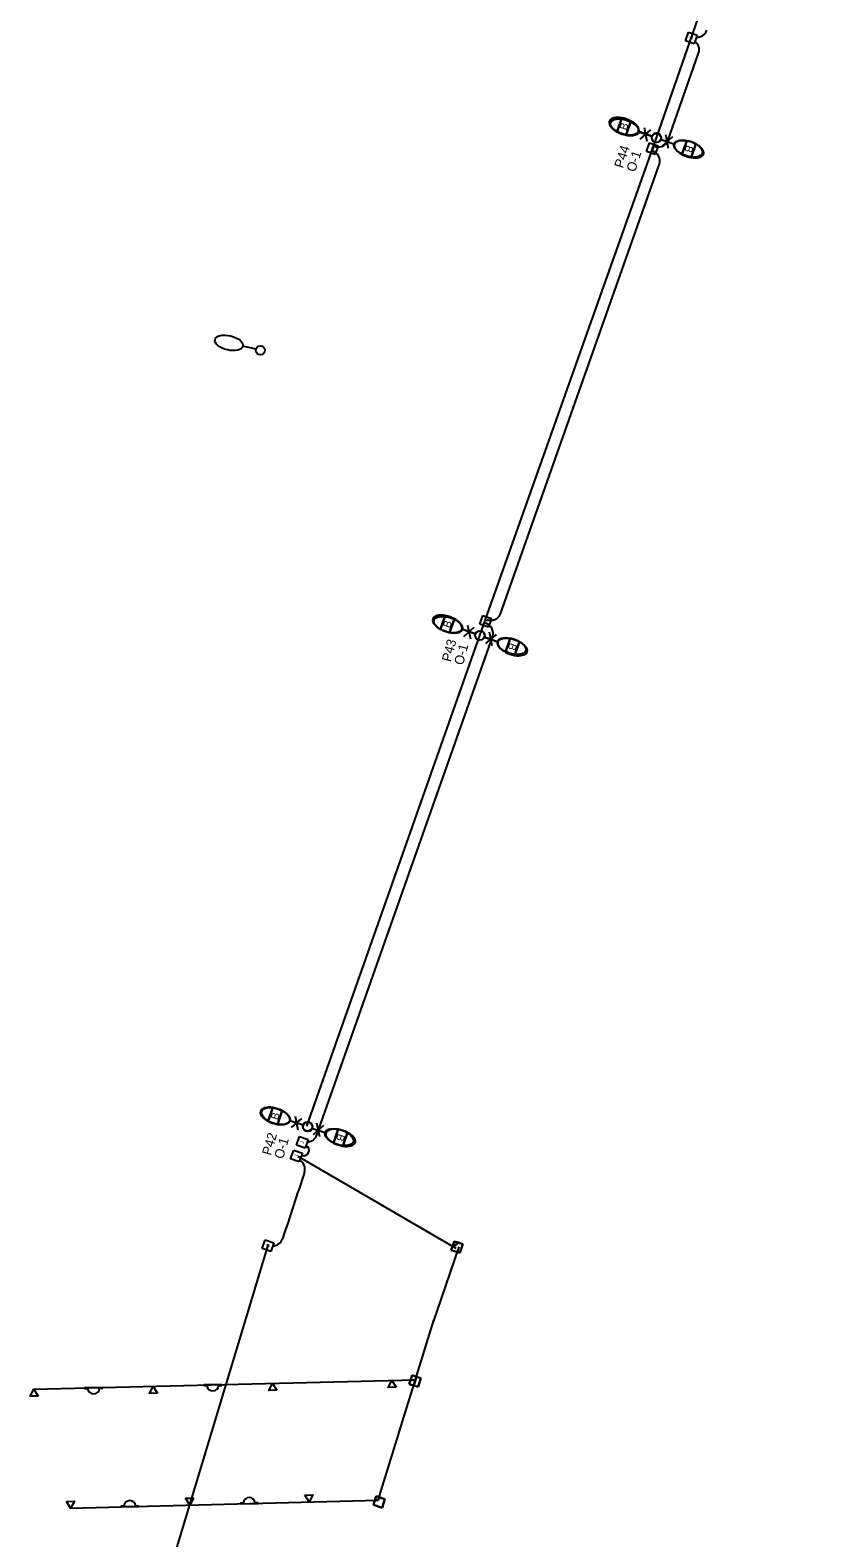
# Model space of a CAD drawing. Extents: x 925407 to 930994, y 604905 to 637063.
# Drawn here: x 929710 to 930127, y 615898 to 616694 of the extents above; entities that cross this region are included whole.
import ezdxf

# ---------------------------------------------------------------- set-up
doc = ezdxf.new("R2010")
doc.units = 0
for name, color, linetype in [('ActivePointCell_dp', 7, 'Continuous'), ('Conduit', 7, 'Continuous'), ('ConduitDB', 7, 'Continuous'), ('ConduitJB', 7, 'Continuous'), ('ConduitOT', 7, 'Continuous'), ('LightingMisc', 7, 'Continuous'), ('LiteCond_ep', 7, 'Continuous'), ('Miscellaneous2', 7, 'Continuous'), ('Miscellaneous9', 7, 'Continuous'), ('PoleLight', 7, 'Continuous'), ('PoleLight_ep', 7, 'Continuous'), ('PullBox', 7, 'Continuous')]:
    doc.layers.add(name, color=color, linetype=linetype)

msp = doc.modelspace()

# ---------------------------------------------------------------- linework, layer by layer
at = {"layer": 'Conduit'}
msp.add_line((929771.65, 615840.13), (929836, 616053.28), dxfattribs=at)
at = {"layer": 'ConduitDB'}
msp.add_line((929851.41, 616099.82), (929934.9, 616051.24), dxfattribs=at)
at = {"layer": 'ConduitJB'}
for p, q in [((929922.77, 616011.3), (929936.59, 616051.85)), ((929893.95, 615918.16), (929923.37, 616013.22)), ((929712.17, 615976.73), (929913.6, 615981.67)), ((929731.47, 615913.95), (929893.95, 615918.16))]:
    msp.add_line(p, q, dxfattribs=at)
at = {"layer": 'ConduitOT'}
for p, q in [((930046.76, 616635.93), (930063.08, 616682.14)), ((929958.53, 616386.13), (930042.49, 616623.84)), ((929861.48, 616111.04), (929954.4, 616374.36))]:
    msp.add_line(p, q, dxfattribs=at)
for centre, radius, start, end in [((930062.2, 616696.15), 5.5, 267.75799, 340.54751), ((930057.9, 616683.98), 5.5, 340.5475, 53.14079), ((930041.68, 616638.09), 5.5, 246.36769, 337.13488), ((930037.15, 616625.25), 5.5, 343.96012, 74.72731), ((929949.11, 616375.86), 5.5, 344.189, 74.95619), ((929953.46, 616388.26), 5.5, 246.36769, 337.13488), ((929856.26, 616112.78), 5.5, 270.50944, 341.59947), ((929854.62, 616102.89), 2.83, 246.23781, 64.18062), ((929849.77, 616092.9), 5.5, 343.32843, 64.09328), ((934163.03, 614647.9), 4543.37, 161.4762, 161.94224), ((929838.22, 616057.94), 5.5, 270.74519, 341.94224)]:
    msp.add_arc(centre, radius, start, end, dxfattribs=at)
at = {"layer": 'LightingMisc'}
for p, q in [((929748.44, 615977.57), (929738.89, 615977.44)), ((929738.89, 615977.44), (929738.89, 615977.12)), ((929738.89, 615977.12), (929740.5, 615977.14)), ((929746.84, 615977.23), (929748.45, 615977.25)), ((929748.45, 615977.25), (929748.44, 615977.57)), ((929811.41, 615979.11), (929801.89, 615978.98)), ((929801.89, 615978.98), (929801.89, 615978.66)), ((929801.89, 615978.66), (929803.5, 615978.69)), ((929809.81, 615978.77), (929811.41, 615978.79)), ((929811.41, 615978.79), (929811.41, 615979.11)), ((929759.65, 615915.07), (929758.04, 615915.07)), ((929758.04, 615915.07), (929758.04, 615914.75)), ((929758.04, 615914.75), (929767.56, 615914.77)), ((929767.56, 615915.08), (929765.96, 615915.08)), ((929767.56, 615914.77), (929767.56, 615915.08)), ((929822.7, 615916.65), (929821.09, 615916.63)), ((929821.09, 615916.63), (929821.1, 615916.31)), ((929821.1, 615916.31), (929830.62, 615916.47)), ((929830.61, 615916.79), (929829.01, 615916.76)), ((929830.62, 615916.47), (929830.61, 615916.79))]:
    msp.add_line(p, q, dxfattribs=at)
for points in [[(929714.37, 615973.13), (929710.15, 615973.03), (929712.17, 615976.73)], [(929777.35, 615974.67), (929773.14, 615974.57), (929775.16, 615978.27)], [(929840.34, 615976.22), (929836.12, 615976.11), (929838.14, 615979.82)], [(929903.32, 615977.76), (929899.11, 615977.66), (929901.13, 615981.36)], [(929855.23, 615920.81), (929859.44, 615920.91), (929857.42, 615917.21)], [(929729.27, 615917.55), (929733.49, 615917.65), (929731.47, 615913.95)], [(929792.25, 615919.18), (929796.46, 615919.28), (929794.45, 615915.58)]]:
    msp.add_lwpolyline(points, close=True, dxfattribs=at)
for centre, radius, start, end in [((929743.66, 615977.5), 3.19, 186.51447, 355.03606), ((929806.65, 615979.05), 3.17, 186.51447, 355.03606), ((929825.86, 615916.39), 3.17, 6.73484, 175.25643), ((929762.8, 615914.76), 3.17, 5.84648, 174.36807)]:
    msp.add_arc(centre, radius, start, end, dxfattribs=at)
at = {"layer": 'LiteCond_ep'}
for p, q in [((930040.78, 616637.4), (930127.1, 616884.67)), ((929947.62, 616374.73), (930040.78, 616637.4)), ((929856.15, 616115.69), (929947.62, 616374.73)), ((929933.98, 616054.83), (929933.29, 616052.69)), ((929935.57, 616054.32), (929933.98, 616054.83)), ((929933.29, 616052.69), (929932.49, 616050.22)), ((929932.49, 616050.22), (929937.1, 616048.73)), ((929935.08, 616052.74), (929933.29, 616052.69)), ((929933.29, 616052.69), (929935.08, 616052.74)), ((929935.57, 616054.32), (929935.08, 616052.74)), ((929935.08, 616052.74), (929935.57, 616054.32)), ((929938.59, 616053.34), (929935.57, 616054.32)), ((929937.1, 616048.73), (929938.59, 616053.34)), ((929911.82, 615984.1), (929911.01, 615981.6)), ((929914.12, 615983.35), (929911.82, 615984.1)), ((929913.6, 615981.67), (929914.12, 615983.35)), ((929916.43, 615982.61), (929914.12, 615983.35)), ((929911.01, 615981.6), (929910.33, 615979.48)), ((929910.33, 615979.48), (929912.69, 615978.72)), ((929913.6, 615981.67), (929911.01, 615981.6)), ((929911.01, 615981.6), (929913.6, 615981.67)), ((929912.69, 615978.72), (929913.6, 615981.67)), ((929912.69, 615978.72), (929914.94, 615978)), ((929914.94, 615978), (929916.43, 615982.61)), ((929892.85, 615920.24), (929892.16, 615918.11)), ((929894.43, 615919.73), (929892.85, 615920.24)), ((929894.43, 615919.73), (929893.95, 615918.16)), ((929893.95, 615918.16), (929894.43, 615919.73)), ((929897.46, 615918.76), (929894.43, 615919.73)), ((929892.16, 615918.11), (929891.36, 615915.63)), ((929891.36, 615915.63), (929895.97, 615914.15)), ((929893.95, 615918.16), (929892.16, 615918.11)), ((929892.16, 615918.11), (929893.95, 615918.16)), ((929895.97, 615914.15), (929897.46, 615918.76))]:
    msp.add_line(p, q, dxfattribs=at)
msp.add_lwpolyline([(929914.12, 615983.35), (929913.6, 615981.67), (929912.69, 615978.72)], dxfattribs=at)
at = {"layer": 'Miscellaneous2'}
for p, q in [((930022.57, 616648.06), (930020.01, 616640.84)), ((930022.57, 616648.06), (930022.57, 616648.06)), ((930024.82, 616639.14), (930027.38, 616646.37)), ((930027.38, 616646.37), (930027.38, 616646.37)), ((930056.84, 616635.96), (930054.29, 616628.73)), ((930056.84, 616635.96), (930056.84, 616635.96)), ((930059.1, 616627.03), (930061.65, 616634.26)), ((930061.65, 616634.26), (930061.65, 616634.26)), ((929929.35, 616385.24), (929926.8, 616378.02)), ((929929.35, 616385.24), (929929.35, 616385.24)), ((929931.61, 616376.32), (929934.16, 616383.55)), ((929934.16, 616383.55), (929934.16, 616383.55)), ((929963.63, 616373.14), (929961.08, 616365.91)), ((929963.63, 616373.14), (929963.63, 616373.14)), ((929965.89, 616364.21), (929968.44, 616371.44)), ((929968.44, 616371.44), (929968.44, 616371.44)), ((929838.32, 616125.48), (929835.9, 616118.2)), ((929838.32, 616125.48), (929838.32, 616125.48)), ((929840.74, 616116.59), (929843.16, 616123.86)), ((929843.16, 616123.86), (929843.16, 616123.86)), ((929872.81, 616113.99), (929870.39, 616106.72)), ((929872.81, 616113.99), (929872.81, 616113.99)), ((929875.23, 616105.11), (929877.65, 616112.38)), ((929877.65, 616112.38), (929877.65, 616112.38))]:
    msp.add_line(p, q, dxfattribs=at)
for centre, major_axis, start_param, end_param in [((930023.69, 616643.6), (7.62, -2.69), 1.249648, 1.891946), ((930023.69, 616643.6), (7.62, -2.69), 4.391241, 4.391271), ((930023.69, 616643.6), (7.62, -2.69), 4.391271, 5.033538), ((930057.97, 616631.5), (7.62, -2.69), 1.249648, 1.891946), ((930057.97, 616631.5), (7.62, -2.69), 4.391241, 4.391271), ((930057.97, 616631.5), (7.62, -2.69), 4.391271, 5.033538), ((929930.48, 616380.78), (7.62, -2.69), 1.249648, 1.891946), ((929930.48, 616380.78), (7.62, -2.69), 4.391241, 4.391271), ((929930.48, 616380.78), (7.62, -2.69), 4.391271, 5.033538), ((929964.76, 616368.68), (7.62, -2.69), 1.249648, 1.891946), ((929964.76, 616368.68), (7.62, -2.69), 4.391241, 4.391271), ((929964.76, 616368.68), (7.62, -2.69), 4.391271, 5.033538), ((929839.53, 616121.03), (7.66, -2.55), 1.249648, 1.891946), ((929839.53, 616121.03), (7.66, -2.55), 4.391241, 4.391271), ((929839.53, 616121.03), (7.66, -2.55), 4.391271, 5.033538), ((929874.02, 616109.55), (7.66, -2.55), 1.249648, 1.891946), ((929874.02, 616109.55), (7.66, -2.55), 4.391241, 4.391271), ((929874.02, 616109.55), (7.66, -2.55), 4.391271, 5.033538)]:
    msp.add_ellipse(centre, major_axis=major_axis, ratio=0.5, start_param=start_param, end_param=end_param, dxfattribs=at)
at = {"layer": 'PoleLight'}
for p, q in [((930020.01, 616640.84), (930022.57, 616648.06)), ((930027.38, 616646.37), (930024.82, 616639.14)), ((930038.45, 616638.39), (930031.31, 616640.91)), ((930043.21, 616636.71), (930050.36, 616634.19)), ((930054.29, 616628.73), (930056.84, 616635.96)), ((930061.65, 616634.26), (930059.1, 616627.03)), ((929926.8, 616378.02), (929929.35, 616385.24)), ((929934.16, 616383.55), (929931.61, 616376.32)), ((929945.24, 616375.57), (929938.1, 616378.09)), ((929950, 616373.89), (929957.14, 616371.37)), ((929961.08, 616365.91), (929963.63, 616373.14)), ((929968.44, 616371.44), (929965.89, 616364.21)), ((929835.9, 616118.2), (929838.32, 616125.48)), ((929843.16, 616123.86), (929840.74, 616116.59)), ((929854.38, 616116.09), (929847.19, 616118.48)), ((929859.17, 616114.49), (929866.35, 616112.1)), ((929870.39, 616106.72), (929872.81, 616113.99)), ((929877.65, 616112.38), (929875.23, 616105.11))]:
    msp.add_line(p, q, dxfattribs=at)
for centre in [(930040.83, 616637.55), (930040.83, 616637.55), (929947.62, 616374.73), (929947.62, 616374.73), (929856.77, 616115.29), (929856.77, 616115.29)]:
    msp.add_circle(centre, 2.52, dxfattribs=at)
for centre, major_axis in [((930023.69, 616643.6), (7.62, -2.69)), ((930057.97, 616631.5), (7.62, -2.69)), ((929930.48, 616380.78), (7.62, -2.69)), ((929964.76, 616368.68), (7.62, -2.69)), ((929839.53, 616121.03), (7.66, -2.55)), ((929874.02, 616109.55), (7.66, -2.55))]:
    msp.add_ellipse(centre, major_axis=major_axis, ratio=0.5, dxfattribs=at)
for centre, major_axis, start_param, end_param in [((930023.69, 616643.6), (7.62, -2.69), 1.891945, 4.391241), ((930023.69, 616643.6), (7.62, -2.69), 0.847605, 1.249648), ((930023.69, 616643.6), (7.62, -2.69), 0, 0.847605), ((930023.69, 616643.6), (7.62, -2.69), 5.033538, 6.283185), ((930057.97, 616631.5), (7.62, -2.69), 1.891945, 4.391241), ((930057.97, 616631.5), (7.62, -2.69), 5.033538, 6.283185), ((930057.97, 616631.5), (7.62, -2.69), 0.847605, 1.249648), ((930057.97, 616631.5), (7.62, -2.69), 0, 0.847605), ((929930.48, 616380.78), (7.62, -2.69), 1.891945, 4.391241), ((929930.48, 616380.78), (7.62, -2.69), 0.847605, 1.249648), ((929930.48, 616380.78), (7.62, -2.69), 0, 0.847605), ((929930.48, 616380.78), (7.62, -2.69), 5.033538, 6.283185), ((929964.76, 616368.68), (7.62, -2.69), 1.891945, 4.391241), ((929964.76, 616368.68), (7.62, -2.69), 5.033538, 6.283185), ((929964.76, 616368.68), (7.62, -2.69), 0.847605, 1.249648), ((929964.76, 616368.68), (7.62, -2.69), 0, 0.847605), ((929839.53, 616121.03), (7.66, -2.55), 1.891945, 4.391241), ((929839.53, 616121.03), (7.66, -2.55), 5.033538, 6.283185), ((929839.53, 616121.03), (7.66, -2.55), 0.847605, 1.249648), ((929839.53, 616121.03), (7.66, -2.55), 0, 0.847605), ((929874.02, 616109.55), (7.66, -2.55), 1.891945, 4.391241), ((929874.02, 616109.55), (7.66, -2.55), 0.847605, 1.249648), ((929874.02, 616109.55), (7.66, -2.55), 0, 0.847605), ((929874.02, 616109.55), (7.66, -2.55), 5.033538, 6.283185)]:
    msp.add_ellipse(centre, major_axis=major_axis, ratio=0.5, start_param=start_param, end_param=end_param, dxfattribs=at)
at = {"layer": 'PoleLight_ep'}
for p, q in [((930038.46, 616638.18), (930031.48, 616640.5)), ((930032.28, 616636.84), (930037.78, 616641.72)), ((930034.29, 616642.88), (930035.77, 616635.68)), ((930043.11, 616636.63), (930050.08, 616634.31)), ((930049.29, 616637.97), (930043.79, 616633.09)), ((930047.27, 616631.93), (930045.8, 616639.13)), ((929829.41, 616525.84), (929822.5, 616527.47)), ((929945.3, 616375.5), (929938.32, 616377.83)), ((929939.12, 616374.16), (929944.62, 616379.04)), ((929941.13, 616380.2), (929942.6, 616373)), ((929949.94, 616373.95), (929956.92, 616371.63)), ((929956.12, 616375.29), (929950.63, 616370.42)), ((929954.11, 616369.25), (929952.64, 616376.46)), ((929854.26, 616116.19), (929847.28, 616118.51)), ((929848.08, 616114.85), (929853.58, 616119.72)), ((929850.09, 616120.89), (929851.56, 616113.68)), ((929858.9, 616114.64), (929865.88, 616112.31)), ((929865.08, 616115.98), (929859.59, 616111.1)), ((929863.07, 616109.94), (929861.6, 616117.14))]:
    msp.add_line(p, q, dxfattribs=at)
for centre, radius in [((930040.78, 616637.4), 2.45), ((929831.71, 616525.29), 2.37), ((929947.62, 616374.73), 2.45), ((929856.58, 616115.41), 2.45)]:
    msp.add_circle(centre, radius, dxfattribs=at)
for centre, major_axis in [((930024.05, 616642.98), (-7.44, 2.48)), ((930057.52, 616631.83), (7.44, -2.48)), ((929815.13, 616529.2), (-7.37, 1.74)), ((929930.88, 616380.3), (-7.44, 2.48)), ((929964.36, 616369.16), (7.44, -2.48)), ((929839.84, 616120.98), (-7.44, 2.48)), ((929873.32, 616109.84), (7.44, -2.48))]:
    msp.add_ellipse(centre, major_axis=major_axis, ratio=0.5, dxfattribs=at)
at = {"layer": 'PullBox'}
for p, q in [((930056.19, 616688.72), (930057.77, 616693.3)), ((930057.77, 616693.3), (930062.35, 616691.72)), ((930062.35, 616691.72), (930060.77, 616687.14)), ((930060.77, 616687.14), (930056.19, 616688.72)), ((930035.6, 616630.31), (930037.2, 616634.88)), ((930040.17, 616628.7), (930035.6, 616630.31)), ((930037.2, 616634.88), (930041.77, 616633.28)), ((930041.77, 616633.28), (930040.17, 616628.7)), ((929947.53, 616380.76), (929949.13, 616385.33)), ((929949.13, 616385.33), (929953.7, 616383.73)), ((929953.7, 616383.73), (929952.1, 616379.15)), ((929952.1, 616379.15), (929947.53, 616380.76)), ((929847.69, 616098.44), (929849.29, 616103.01)), ((929849.29, 616103.01), (929853.87, 616101.41)), ((929850.76, 616105.57), (929852.37, 616110.14)), ((929855.33, 616103.96), (929850.76, 616105.57)), ((929852.37, 616110.14), (929856.94, 616108.54)), ((929856.94, 616108.54), (929855.33, 616103.96)), ((929852.26, 616096.83), (929847.69, 616098.44)), ((929853.87, 616101.41), (929852.26, 616096.83)), ((929832.65, 616051), (929834.25, 616055.57)), ((929834.25, 616055.57), (929838.83, 616053.97)), ((929932.49, 616050.22), (929933.98, 616054.83)), ((929933.98, 616054.83), (929938.59, 616053.34)), ((929837.22, 616049.4), (929832.65, 616051)), ((929838.83, 616053.97), (929837.22, 616049.4)), ((929937.1, 616048.73), (929932.49, 616050.22)), ((929938.59, 616053.34), (929937.1, 616048.73)), ((929910.33, 615979.48), (929911.82, 615984.1)), ((929911.82, 615984.1), (929916.43, 615982.61)), ((929914.94, 615978), (929910.33, 615979.48)), ((929916.43, 615982.61), (929914.94, 615978)), ((929891.36, 615915.63), (929892.85, 615920.24)), ((929892.85, 615920.24), (929897.46, 615918.76)), ((929895.97, 615914.15), (929891.36, 615915.63)), ((929897.46, 615918.76), (929895.97, 615914.15))]:
    msp.add_line(p, q, dxfattribs=at)

# ---------------------------------------------------------------- texts
at = {"layer": 'ActivePointCell_dp'}
for s, rotation, p in [('P44', 72.21332, (930023.17, 616621.14)), ('O-1', 72.21332, (930029.55, 616619.09)), ('P43', 75.18661, (929932.23, 616360.47)), ('O-1', 75.18661, (929938.71, 616358.76)), ('P42', 73.75868, (929837.25, 616099.89)), ('O-1', 73.75868, (929843.68, 616098.02))]:
    msp.add_text(s, height=5, rotation=rotation, dxfattribs=at).set_placement(p)
at = {"layer": 'Miscellaneous9'}
for rotation, p in [(70.54853, (930025, 616641.16)), (250.54853, (930056.67, 616633.93)), (70.54853, (929931.78, 616378.35)), (250.54853, (929963.46, 616371.11)), (71.58063, (929840.87, 616118.62)), (251.58063, (929872.67, 616111.96))]:
    msp.add_text('B', height=4.08, rotation=rotation, dxfattribs=at).set_placement(p)
at = {"layer": 'PullBox'}
for rotation, p in [(70.97438, (930059.97, 616689.28)), (70.66194, (930039.38, 616630.85)), (70.66194, (929951.31, 616381.3)), (70.66194, (929854.55, 616106.11)), (70.66194, (929851.47, 616098.98)), (70.66194, (929836.43, 616051.54))]:
    msp.add_text('J', height=1.94, rotation=rotation, dxfattribs=at).set_placement(p)

doc.saveas('drawing.dxf')
